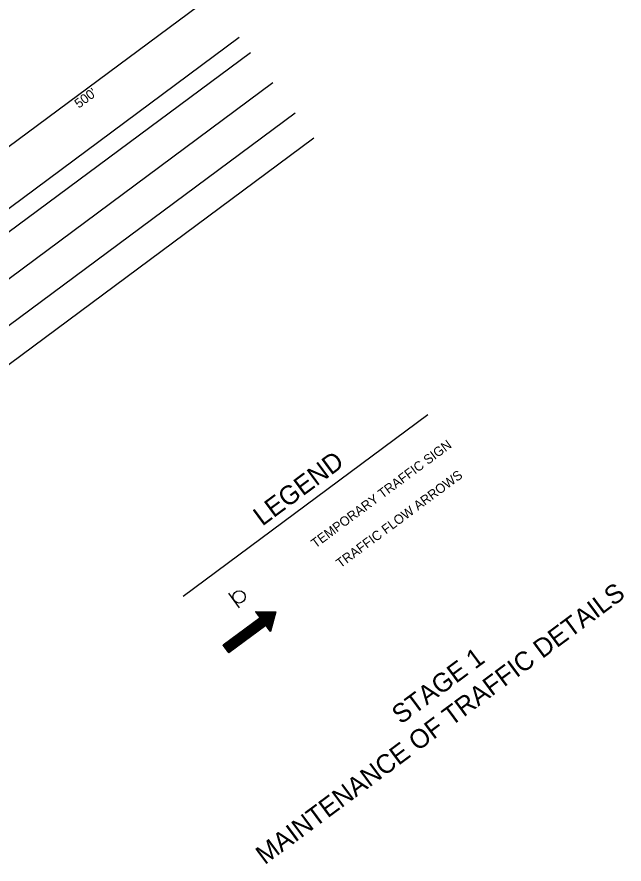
# Model space of a CAD drawing. Extents: x 998982 to 1000626, y 1875366 to 1876934.
# Drawn here: x 1000239 to 1000626, y 1875968 to 1876508 of the extents above; entities that cross this region are included whole.
import ezdxf

# ---------------------------------------------------------------- set-up
doc = ezdxf.new("R2010")
doc.units = 0
for name, color, linetype in [('R_Border Prem', 7, 'Continuous'), ('R_Draft', 7, 'Continuous'), ('STAMP', 7, 'Continuous')]:
    doc.layers.add(name, color=color, linetype=linetype)

msp = doc.modelspace()

# ---------------------------------------------------------------- linework, layer by layer
at = {"layer": 'R_Border Prem'}
for p, q in [((1000344.91, 1876138.97), (1000500.6, 1876254.57)), ((1000390.92, 1876129.06), (1000390.93, 1876129.13)), ((1000391.01, 1876128.94), (1000391.03, 1876129.13)), ((1000391.09, 1876128.83), (1000391.14, 1876129.12)), ((1000391.18, 1876128.72), (1000391.24, 1876129.12)), ((1000391.26, 1876128.6), (1000391.34, 1876129.12)), ((1000391.29, 1876115.77), (1000392.52, 1876124.14)), ((1000391.34, 1876128.49), (1000391.44, 1876129.12)), ((1000391.4, 1876115.86), (1000392.64, 1876124.23)), ((1000391.43, 1876128.37), (1000391.54, 1876129.12)), ((1000391.51, 1876128.26), (1000391.64, 1876129.11)), ((1000391.51, 1876115.94), (1000392.75, 1876124.31)), ((1000391.6, 1876128.15), (1000391.74, 1876129.11)), ((1000391.63, 1876116.02), (1000392.86, 1876124.4)), ((1000391.68, 1876128.03), (1000391.84, 1876129.11)), ((1000391.74, 1876116.11), (1000392.98, 1876124.48)), ((1000391.77, 1876127.92), (1000391.94, 1876129.11)), ((1000391.85, 1876127.81), (1000392.04, 1876129.11)), ((1000391.85, 1876116.19), (1000393.09, 1876124.57)), ((1000391.93, 1876127.69), (1000392.14, 1876129.11)), ((1000391.97, 1876116.28), (1000393.2, 1876124.65)), ((1000392.02, 1876127.58), (1000392.24, 1876129.1)), ((1000392.08, 1876116.36), (1000393.32, 1876124.73)), ((1000392.1, 1876127.47), (1000392.34, 1876129.1)), ((1000392.19, 1876127.35), (1000392.45, 1876129.1)), ((1000392.19, 1876116.45), (1000393.43, 1876124.82)), ((1000392.27, 1876127.24), (1000392.55, 1876129.1)), ((1000392.31, 1876116.53), (1000393.54, 1876124.9)), ((1000392.36, 1876127.13), (1000392.65, 1876129.1)), ((1000392.42, 1876116.61), (1000393.66, 1876124.99)), ((1000392.44, 1876127.01), (1000392.75, 1876129.09)), ((1000392.52, 1876126.9), (1000392.85, 1876129.09)), ((1000392.53, 1876116.7), (1000393.77, 1876125.07)), ((1000392.61, 1876126.79), (1000392.95, 1876129.09)), ((1000392.65, 1876116.78), (1000394.46, 1876129.06)), ((1000392.69, 1876126.67), (1000393.05, 1876129.09)), ((1000392.76, 1876116.87), (1000394.56, 1876129.06)), ((1000392.78, 1876126.56), (1000393.15, 1876129.09)), ((1000392.86, 1876126.44), (1000393.25, 1876129.09)), ((1000392.87, 1876116.95), (1000394.66, 1876129.06)), ((1000392.95, 1876126.33), (1000393.35, 1876129.08)), ((1000392.99, 1876117.04), (1000394.76, 1876129.06)), ((1000393.03, 1876126.22), (1000393.45, 1876129.08)), ((1000393.1, 1876117.12), (1000394.87, 1876129.06)), ((1000393.12, 1876126.1), (1000393.55, 1876129.08)), ((1000393.2, 1876125.99), (1000393.66, 1876129.08)), ((1000393.22, 1876117.2), (1000394.97, 1876129.06)), ((1000393.28, 1876125.88), (1000393.76, 1876129.08)), ((1000393.33, 1876117.29), (1000395.07, 1876129.05)), ((1000393.37, 1876125.76), (1000393.86, 1876129.08)), ((1000393.44, 1876117.37), (1000395.17, 1876129.05)), ((1000393.45, 1876125.65), (1000393.96, 1876129.07)), ((1000393.54, 1876125.54), (1000394.06, 1876129.07)), ((1000393.56, 1876117.46), (1000395.27, 1876129.05)), ((1000393.62, 1876125.42), (1000394.16, 1876129.07)), ((1000393.67, 1876117.54), (1000395.37, 1876129.05)), ((1000393.71, 1876125.31), (1000394.26, 1876129.07)), ((1000393.78, 1876117.63), (1000395.47, 1876129.05)), ((1000393.79, 1876125.2), (1000394.36, 1876129.07)), ((1000393.9, 1876117.71), (1000395.57, 1876129.04)), ((1000394.01, 1876117.79), (1000395.67, 1876129.04)), ((1000394.12, 1876117.88), (1000395.77, 1876129.04)), ((1000394.24, 1876117.96), (1000395.87, 1876129.04)), ((1000394.35, 1876118.05), (1000395.97, 1876129.04)), ((1000394.46, 1876118.13), (1000396.08, 1876129.04)), ((1000394.58, 1876118.22), (1000396.18, 1876129.03)), ((1000394.69, 1876118.3), (1000396.28, 1876129.03)), ((1000394.8, 1876118.39), (1000396.38, 1876129.03)), ((1000394.92, 1876118.47), (1000396.48, 1876129.03)), ((1000395.03, 1876118.55), (1000396.58, 1876129.03)), ((1000395.15, 1876118.64), (1000396.68, 1876129.02)), ((1000395.26, 1876118.72), (1000396.78, 1876129.02)), ((1000395.37, 1876118.81), (1000396.88, 1876129.02)), ((1000395.49, 1876118.89), (1000396.98, 1876129.02)), ((1000395.6, 1876118.98), (1000397.08, 1876129.02)), ((1000395.71, 1876119.06), (1000397.18, 1876129.02)), ((1000395.83, 1876119.14), (1000397.29, 1876129.01)), ((1000395.94, 1876119.23), (1000397.39, 1876129.01)), ((1000396.05, 1876119.31), (1000397.49, 1876129.01)), ((1000396.17, 1876119.4), (1000397.59, 1876129.01)), ((1000396.28, 1876119.48), (1000397.69, 1876129.01)), ((1000396.39, 1876119.57), (1000397.79, 1876129)), ((1000396.51, 1876119.65), (1000397.89, 1876129)), ((1000396.62, 1876119.73), (1000397.99, 1876129)), ((1000396.74, 1876119.82), (1000398.09, 1876129)), ((1000396.85, 1876119.9), (1000398.19, 1876129)), ((1000396.96, 1876119.99), (1000398.29, 1876129)), ((1000397.08, 1876120.07), (1000398.39, 1876128.99)), ((1000397.19, 1876120.16), (1000398.49, 1876128.99)), ((1000397.3, 1876120.24), (1000398.6, 1876128.99)), ((1000397.41, 1876120.31), (1000398.7, 1876128.99)), ((1000397.5, 1876120.2), (1000398.8, 1876128.99)), ((1000397.58, 1876120.09), (1000398.9, 1876128.99)), ((1000397.67, 1876119.97), (1000399, 1876128.98)), ((1000397.75, 1876119.86), (1000399.1, 1876128.98)), ((1000397.84, 1876119.75), (1000399.2, 1876128.98)), ((1000397.92, 1876119.63), (1000399.3, 1876128.98)), ((1000398, 1876119.52), (1000399.4, 1876128.98)), ((1000398.09, 1876119.4), (1000399.5, 1876128.97)), ((1000398.17, 1876119.29), (1000399.6, 1876128.97)), ((1000398.26, 1876119.18), (1000399.7, 1876128.97)), ((1000398.34, 1876119.06), (1000399.81, 1876128.97)), ((1000398.43, 1876118.95), (1000399.91, 1876128.97)), ((1000398.51, 1876118.84), (1000400.01, 1876128.97)), ((1000398.6, 1876118.72), (1000400.11, 1876128.96)), ((1000398.68, 1876118.61), (1000400.21, 1876128.96)), ((1000398.76, 1876118.5), (1000400.31, 1876128.96)), ((1000398.85, 1876118.38), (1000400.41, 1876128.96)), ((1000398.93, 1876118.27), (1000400.51, 1876128.96)), ((1000399.02, 1876118.16), (1000400.61, 1876128.95)), ((1000399.1, 1876118.04), (1000400.71, 1876128.95)), ((1000399.19, 1876117.93), (1000400.81, 1876128.95)), ((1000399.27, 1876117.82), (1000400.91, 1876128.95)), ((1000399.35, 1876117.7), (1000401.02, 1876128.95)), ((1000399.44, 1876117.59), (1000401.12, 1876128.95)), ((1000399.52, 1876117.47), (1000401.22, 1876128.94)), ((1000399.61, 1876117.36), (1000401.32, 1876128.94)), ((1000399.69, 1876117.25), (1000401.42, 1876128.94)), ((1000399.78, 1876117.13), (1000401.52, 1876128.94)), ((1000399.86, 1876117.02), (1000401.62, 1876128.94)), ((1000399.94, 1876116.91), (1000401.72, 1876128.93)), ((1000400.03, 1876116.79), (1000401.82, 1876128.93)), ((1000400.11, 1876116.68), (1000401.92, 1876128.93)), ((1000400.2, 1876116.57), (1000402.02, 1876128.93)), ((1000400.28, 1876116.45), (1000402.12, 1876128.93)), ((1000400.37, 1876116.34), (1000402.23, 1876128.93)), ((1000400.55, 1876116.91), (1000402.33, 1876128.92)), ((1000400.76, 1876117.66), (1000402.43, 1876128.92)), ((1000400.97, 1876118.41), (1000402.53, 1876128.92)), ((1000401.19, 1876119.15), (1000402.63, 1876128.92)), ((1000401.4, 1876119.9), (1000402.73, 1876128.92)), ((1000401.61, 1876120.65), (1000402.83, 1876128.92)), ((1000401.82, 1876121.4), (1000402.93, 1876128.91)), ((1000402.03, 1876122.15), (1000403.03, 1876128.91)), ((1000402.24, 1876122.9), (1000403.13, 1876128.91)), ((1000402.46, 1876123.65), (1000403.23, 1876128.91)), ((1000402.67, 1876124.4), (1000403.33, 1876128.91)), ((1000402.88, 1876125.15), (1000403.44, 1876128.9)), ((1000403.09, 1876125.89), (1000403.54, 1876128.9)), ((1000403.3, 1876126.64), (1000403.64, 1876128.9)), ((1000403.51, 1876127.39), (1000403.74, 1876128.9)), ((1000403.73, 1876128.14), (1000403.84, 1876128.9)), ((1000403.94, 1876128.89), (1000403.94, 1876128.9)), ((1000384.02, 1876110.38), (1000385.26, 1876118.75)), ((1000384.13, 1876110.46), (1000385.37, 1876118.83)), ((1000384.25, 1876110.54), (1000385.48, 1876118.92)), ((1000384.36, 1876110.63), (1000385.6, 1876119)), ((1000384.47, 1876110.71), (1000385.71, 1876119.09)), ((1000384.59, 1876110.8), (1000385.82, 1876119.17)), ((1000384.7, 1876110.88), (1000385.94, 1876119.25)), ((1000384.81, 1876110.97), (1000386.05, 1876119.34)), ((1000384.93, 1876111.05), (1000386.16, 1876119.42)), ((1000385.04, 1876111.13), (1000386.28, 1876119.51)), ((1000385.15, 1876111.22), (1000386.39, 1876119.59)), ((1000385.27, 1876111.3), (1000386.5, 1876119.68)), ((1000385.38, 1876111.39), (1000386.62, 1876119.76)), ((1000385.49, 1876111.47), (1000386.73, 1876119.84)), ((1000385.61, 1876111.56), (1000386.85, 1876119.93)), ((1000385.72, 1876111.64), (1000386.96, 1876120.01)), ((1000385.84, 1876111.72), (1000387.07, 1876120.1)), ((1000385.95, 1876111.81), (1000387.19, 1876120.18)), ((1000386.06, 1876111.89), (1000387.3, 1876120.27)), ((1000386.18, 1876111.98), (1000387.41, 1876120.35)), ((1000386.29, 1876112.06), (1000387.53, 1876120.43)), ((1000386.4, 1876112.15), (1000387.64, 1876120.52)), ((1000386.52, 1876112.23), (1000387.75, 1876120.6)), ((1000386.63, 1876112.31), (1000387.87, 1876120.69)), ((1000386.74, 1876112.4), (1000387.98, 1876120.77)), ((1000386.86, 1876112.48), (1000388.09, 1876120.86)), ((1000386.97, 1876112.57), (1000388.21, 1876120.94)), ((1000387.08, 1876112.65), (1000388.32, 1876121.02)), ((1000387.2, 1876112.74), (1000388.43, 1876121.11)), ((1000387.31, 1876112.82), (1000388.55, 1876121.19)), ((1000387.42, 1876112.9), (1000388.66, 1876121.28)), ((1000387.54, 1876112.99), (1000388.78, 1876121.36)), ((1000387.65, 1876113.07), (1000388.89, 1876121.45)), ((1000387.77, 1876113.16), (1000389, 1876121.53)), ((1000387.88, 1876113.24), (1000389.12, 1876121.61)), ((1000387.99, 1876113.33), (1000389.23, 1876121.7)), ((1000388.11, 1876113.41), (1000389.34, 1876121.78)), ((1000388.22, 1876113.5), (1000389.46, 1876121.87)), ((1000388.33, 1876113.58), (1000389.57, 1876121.95)), ((1000388.45, 1876113.66), (1000389.68, 1876122.04)), ((1000388.56, 1876113.75), (1000389.8, 1876122.12)), ((1000388.67, 1876113.83), (1000389.91, 1876122.2)), ((1000388.79, 1876113.92), (1000390.02, 1876122.29)), ((1000388.9, 1876114), (1000390.14, 1876122.37)), ((1000389.01, 1876114.09), (1000390.25, 1876122.46)), ((1000389.13, 1876114.17), (1000390.36, 1876122.54)), ((1000389.24, 1876114.25), (1000390.48, 1876122.63)), ((1000389.35, 1876114.34), (1000390.59, 1876122.71)), ((1000389.47, 1876114.42), (1000390.71, 1876122.8)), ((1000389.58, 1876114.51), (1000390.82, 1876122.88)), ((1000389.7, 1876114.59), (1000390.93, 1876122.96)), ((1000389.81, 1876114.68), (1000391.05, 1876123.05)), ((1000389.92, 1876114.76), (1000391.16, 1876123.13)), ((1000390.04, 1876114.84), (1000391.27, 1876123.22)), ((1000390.15, 1876114.93), (1000391.39, 1876123.3)), ((1000390.26, 1876115.01), (1000391.5, 1876123.39)), ((1000390.38, 1876115.1), (1000391.61, 1876123.47)), ((1000390.49, 1876115.18), (1000391.73, 1876123.55)), ((1000390.6, 1876115.27), (1000391.84, 1876123.64)), ((1000390.72, 1876115.35), (1000391.95, 1876123.72)), ((1000390.83, 1876115.43), (1000392.07, 1876123.81)), ((1000390.94, 1876115.52), (1000392.18, 1876123.89)), ((1000391.06, 1876115.6), (1000392.3, 1876123.98)), ((1000391.17, 1876115.69), (1000392.41, 1876124.06)), ((1000376.75, 1876104.98), (1000377.99, 1876113.35)), ((1000376.87, 1876105.06), (1000378.1, 1876113.44)), ((1000376.98, 1876105.15), (1000378.22, 1876113.52)), ((1000377.09, 1876105.23), (1000378.33, 1876113.61)), ((1000377.21, 1876105.32), (1000378.44, 1876113.69)), ((1000377.32, 1876105.4), (1000378.56, 1876113.77)), ((1000377.43, 1876105.49), (1000378.67, 1876113.86)), ((1000377.55, 1876105.57), (1000378.78, 1876113.94)), ((1000377.66, 1876105.65), (1000378.9, 1876114.03)), ((1000377.77, 1876105.74), (1000379.01, 1876114.11)), ((1000377.89, 1876105.82), (1000379.12, 1876114.2)), ((1000378, 1876105.91), (1000379.24, 1876114.28)), ((1000378.11, 1876105.99), (1000379.35, 1876114.36)), ((1000378.23, 1876106.08), (1000379.46, 1876114.45)), ((1000378.34, 1876106.16), (1000379.58, 1876114.53)), ((1000378.45, 1876106.24), (1000379.69, 1876114.62)), ((1000378.57, 1876106.33), (1000379.81, 1876114.7)), ((1000378.68, 1876106.41), (1000379.92, 1876114.79)), ((1000378.8, 1876106.5), (1000380.03, 1876114.87)), ((1000378.91, 1876106.58), (1000380.15, 1876114.95)), ((1000379.02, 1876106.67), (1000380.26, 1876115.04)), ((1000379.14, 1876106.75), (1000380.37, 1876115.12)), ((1000379.25, 1876106.83), (1000380.49, 1876115.21)), ((1000379.36, 1876106.92), (1000380.6, 1876115.29)), ((1000379.48, 1876107), (1000380.71, 1876115.38)), ((1000379.59, 1876107.09), (1000380.83, 1876115.46)), ((1000379.7, 1876107.17), (1000380.94, 1876115.54)), ((1000379.82, 1876107.26), (1000381.05, 1876115.63)), ((1000379.93, 1876107.34), (1000381.17, 1876115.71)), ((1000380.04, 1876107.42), (1000381.28, 1876115.8)), ((1000380.16, 1876107.51), (1000381.4, 1876115.88)), ((1000380.27, 1876107.59), (1000381.51, 1876115.97)), ((1000380.39, 1876107.68), (1000381.62, 1876116.05)), ((1000380.5, 1876107.76), (1000381.74, 1876116.13)), ((1000380.61, 1876107.85), (1000381.85, 1876116.22)), ((1000380.73, 1876107.93), (1000381.96, 1876116.3)), ((1000380.84, 1876108.01), (1000382.08, 1876116.39)), ((1000380.95, 1876108.1), (1000382.19, 1876116.47)), ((1000381.07, 1876108.18), (1000382.3, 1876116.56)), ((1000381.18, 1876108.27), (1000382.42, 1876116.64)), ((1000381.29, 1876108.35), (1000382.53, 1876116.72)), ((1000381.41, 1876108.44), (1000382.64, 1876116.81)), ((1000381.52, 1876108.52), (1000382.76, 1876116.89)), ((1000381.63, 1876108.61), (1000382.87, 1876116.98)), ((1000381.75, 1876108.69), (1000382.98, 1876117.06)), ((1000381.86, 1876108.77), (1000383.1, 1876117.15)), ((1000381.97, 1876108.86), (1000383.21, 1876117.23)), ((1000382.09, 1876108.94), (1000383.33, 1876117.32)), ((1000382.2, 1876109.03), (1000383.44, 1876117.4)), ((1000382.32, 1876109.11), (1000383.55, 1876117.48)), ((1000382.43, 1876109.2), (1000383.67, 1876117.57)), ((1000382.54, 1876109.28), (1000383.78, 1876117.65)), ((1000382.66, 1876109.36), (1000383.89, 1876117.74)), ((1000382.77, 1876109.45), (1000384.01, 1876117.82)), ((1000382.88, 1876109.53), (1000384.12, 1876117.91)), ((1000383, 1876109.62), (1000384.23, 1876117.99)), ((1000383.11, 1876109.7), (1000384.35, 1876118.07)), ((1000383.22, 1876109.79), (1000384.46, 1876118.16)), ((1000383.34, 1876109.87), (1000384.57, 1876118.24)), ((1000383.45, 1876109.95), (1000384.69, 1876118.33)), ((1000383.56, 1876110.04), (1000384.8, 1876118.41)), ((1000383.68, 1876110.12), (1000384.91, 1876118.5)), ((1000383.79, 1876110.21), (1000385.03, 1876118.58)), ((1000383.9, 1876110.29), (1000385.14, 1876118.66)), ((1000370.61, 1876107.19), (1000370.72, 1876107.96)), ((1000370.69, 1876107.07), (1000370.84, 1876108.04)), ((1000370.78, 1876106.96), (1000370.95, 1876108.13)), ((1000370.86, 1876106.85), (1000371.06, 1876108.21)), ((1000370.95, 1876106.73), (1000371.18, 1876108.29)), ((1000371.03, 1876106.62), (1000371.29, 1876108.38)), ((1000371.11, 1876106.51), (1000371.4, 1876108.46)), ((1000371.2, 1876106.39), (1000371.52, 1876108.55)), ((1000371.28, 1876106.28), (1000371.63, 1876108.63)), ((1000371.37, 1876106.17), (1000371.74, 1876108.72)), ((1000371.45, 1876106.05), (1000371.86, 1876108.8)), ((1000371.54, 1876105.94), (1000371.97, 1876108.88)), ((1000371.62, 1876105.82), (1000372.08, 1876108.97)), ((1000371.7, 1876105.71), (1000372.2, 1876109.05)), ((1000371.79, 1876105.6), (1000372.31, 1876109.14)), ((1000371.87, 1876105.48), (1000372.43, 1876109.22)), ((1000371.96, 1876105.37), (1000372.54, 1876109.31)), ((1000372.04, 1876105.26), (1000372.65, 1876109.39)), ((1000372.13, 1876105.14), (1000372.77, 1876109.47)), ((1000372.21, 1876105.03), (1000372.88, 1876109.56)), ((1000372.29, 1876104.92), (1000372.99, 1876109.64)), ((1000372.38, 1876104.8), (1000373.11, 1876109.73)), ((1000372.46, 1876104.69), (1000373.22, 1876109.81)), ((1000372.55, 1876104.58), (1000373.33, 1876109.9)), ((1000372.63, 1876104.46), (1000373.45, 1876109.98)), ((1000372.72, 1876104.35), (1000373.56, 1876110.06)), ((1000372.8, 1876104.23), (1000373.67, 1876110.15)), ((1000372.88, 1876104.12), (1000373.79, 1876110.23)), ((1000372.97, 1876104.01), (1000373.9, 1876110.32)), ((1000373.05, 1876103.89), (1000374.01, 1876110.4)), ((1000373.14, 1876103.78), (1000374.13, 1876110.49)), ((1000373.22, 1876103.67), (1000374.24, 1876110.57)), ((1000373.31, 1876103.55), (1000374.36, 1876110.65)), ((1000373.39, 1876103.44), (1000374.47, 1876110.74)), ((1000373.47, 1876103.33), (1000374.58, 1876110.82)), ((1000373.56, 1876103.21), (1000374.7, 1876110.91)), ((1000373.64, 1876103.1), (1000374.81, 1876110.99)), ((1000373.73, 1876102.99), (1000374.92, 1876111.08)), ((1000373.81, 1876102.87), (1000375.04, 1876111.16)), ((1000373.91, 1876102.87), (1000375.15, 1876111.24)), ((1000374.03, 1876102.96), (1000375.26, 1876111.33)), ((1000374.14, 1876103.04), (1000375.38, 1876111.41)), ((1000374.25, 1876103.13), (1000375.49, 1876111.5)), ((1000374.37, 1876103.21), (1000375.6, 1876111.58)), ((1000374.48, 1876103.29), (1000375.72, 1876111.67)), ((1000374.59, 1876103.38), (1000375.83, 1876111.75)), ((1000374.71, 1876103.46), (1000375.95, 1876111.83)), ((1000374.82, 1876103.55), (1000376.06, 1876111.92)), ((1000374.94, 1876103.63), (1000376.17, 1876112)), ((1000375.05, 1876103.72), (1000376.29, 1876112.09)), ((1000375.16, 1876103.8), (1000376.4, 1876112.17)), ((1000375.28, 1876103.88), (1000376.51, 1876112.26)), ((1000375.39, 1876103.97), (1000376.63, 1876112.34)), ((1000375.5, 1876104.05), (1000376.74, 1876112.43)), ((1000375.62, 1876104.14), (1000376.85, 1876112.51)), ((1000375.73, 1876104.22), (1000376.97, 1876112.59)), ((1000375.84, 1876104.31), (1000377.08, 1876112.68)), ((1000375.96, 1876104.39), (1000377.19, 1876112.76)), ((1000376.07, 1876104.47), (1000377.31, 1876112.85)), ((1000376.18, 1876104.56), (1000377.42, 1876112.93)), ((1000376.3, 1876104.64), (1000377.53, 1876113.02)), ((1000376.41, 1876104.73), (1000377.65, 1876113.1)), ((1000376.52, 1876104.81), (1000377.76, 1876113.18)), ((1000376.64, 1876104.9), (1000377.88, 1876113.27)), ((1000370.36, 1876107.53), (1000370.38, 1876107.7)), ((1000370.44, 1876107.41), (1000370.49, 1876107.79)), ((1000370.52, 1876107.3), (1000370.61, 1876107.87))]:
    msp.add_line(p, q, dxfattribs=at)
at = {"layer": 'R_Draft'}
for p, q in [((1000200.89, 1876401.08), (1000361.46, 1876520.31)), ((1000380.5, 1876494.68), (999829.63, 1876085.64)), ((1000387.64, 1876485.07), (999836.77, 1876076.03)), ((1000401.91, 1876465.85), (999851.04, 1876056.81)), ((1000416.18, 1876446.63), (999865.31, 1876037.59)), ((1000428.07, 1876430.61), (999877.2, 1876021.57)), ((1000393.84, 1876125.12), (1000370.28, 1876107.63)), ((1000393.84, 1876125.12), (1000370.28, 1876107.63)), ((1000390.87, 1876129.13), (1000393.84, 1876125.12)), ((1000390.87, 1876129.13), (1000403.94, 1876128.9)), ((1000390.87, 1876129.13), (1000393.84, 1876125.12)), ((1000390.87, 1876129.13), (1000403.94, 1876128.9)), ((1000403.94, 1876128.9), (1000400.38, 1876116.32)), ((1000403.94, 1876128.9), (1000400.38, 1876116.32)), ((1000397.41, 1876120.32), (1000373.84, 1876102.82)), ((1000397.41, 1876120.32), (1000373.85, 1876102.82)), ((1000397.41, 1876120.32), (1000400.38, 1876116.32)), ((1000397.41, 1876120.32), (1000400.38, 1876116.32)), ((1000370.28, 1876107.63), (1000373.84, 1876102.82)), ((1000370.28, 1876107.63), (1000373.85, 1876102.82))]:
    msp.add_line(p, q, dxfattribs=at)
at = {"layer": 'STAMP'}
msp.add_line((1000380.8, 1876131.42), (1000373.8, 1876140.86), dxfattribs=at)
msp.add_circle((1000380.45, 1876138.47), 3.92, dxfattribs=at)

# ---------------------------------------------------------------- texts
at = {"layer": 'R_Border Prem'}
for s, height, p in [("500'", 6, (1000278.36, 1876449.36)), ('TEMPORARY TRAFFIC SIGN', 6, (1000429.12, 1876169.26)), ('LEGEND', 12, (1000395.22, 1876183.2)), ('TRAFFIC FLOW ARROWS', 6, (1000445.02, 1876156.62)), ('MAINTENANCE OF TRAFFIC DETAILS', 12, (1000396.78, 1875967.52)), ('STAGE 1', 12, (1000483.49, 1876056.94))]:
    msp.add_text(s, height=height, rotation=36.5953, dxfattribs=at).set_placement(p)

doc.saveas('drawing.dxf')
